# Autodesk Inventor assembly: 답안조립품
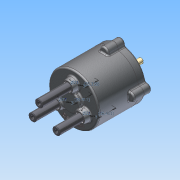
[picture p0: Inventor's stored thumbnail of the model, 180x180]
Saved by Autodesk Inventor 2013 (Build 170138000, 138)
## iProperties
Created: 2014-07
Part Number: 답안조립품
Document SubType Name: Assembly
Designer: SEMTLE01_MAIN
Author: SEMTLE01_MAIN
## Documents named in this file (14)
- C:\Users\성경\Desktop\Inventor1급_강성희\답안조립품.iam
- C:\Users\성경\Desktop\Inventor1급_강성희\몸체.ipt
- C:\Users\성경\Desktop\Inventor1급_강성희\M5x0.5x20.ipt
- C:\Users\성경\Desktop\Inventor1급_강성희\베어링 NA 4900.ipt
- C:\Users\성경\Desktop\Inventor1급_강성희\오일실.ipt
- C:\Users\성경\Desktop\Inventor1급_강성희\커버.ipt
- C:\Users\성경\Desktop\Inventor1급_강성희\멈춤링 10 x 1.ipt
- C:\Users\성경\Desktop\Inventor1급_강성희\멈춤링 22 x 1.2.ipt
- C:\Users\성경\Desktop\Inventor1급_강성희\메인 축.ipt
- C:\Users\성경\Desktop\Inventor1급_강성희\판캠.ipt
- C:\Users\성경\Desktop\Inventor1급_강성희\슬라이드 축.ipt
- C:\Users\성경\Desktop\Inventor1급_강성희\가변스프링01.ipt
- C:\Users\성경\Desktop\Inventor1급_강성희\가변스프링02.ipt
- C:\Users\성경\Desktop\Inventor1급_강성희\가변스프링03.ipt
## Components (7 placed, 4 different names)
1. 가변스프링01:1
2. 가변스프링02:1
3. 가변스프링03:1
4. M5x0.5x20:1
5. M5x0.5x20:2
6. M5x0.5x20:3
7. M5x0.5x20:4
